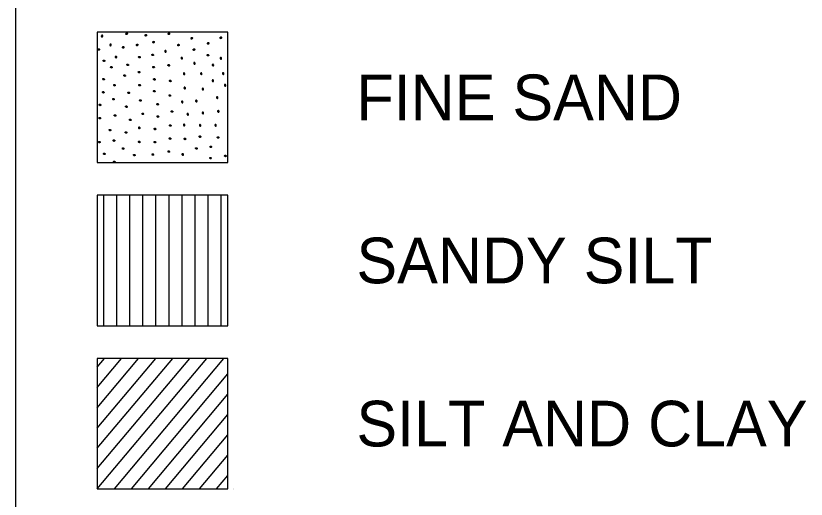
# Model space of a CAD drawing. Extents: x -59 to 43, y 0 to 22.
# Drawn here: x 11.667 to 14.091, y 17.983 to 19.465 of the extents above; entities that cross this region are included whole.
import ezdxf

# ---------------------------------------------------------------- set-up
doc = ezdxf.new("R2010")
doc.units = 0
for name, color, linetype in [('Default', 7, 'Continuous'), ('SH_Data', 7, 'Continuous'), ('SH_Text', 7, 'Continuous')]:
    doc.layers.add(name, color=color, linetype=linetype)

msp = doc.modelspace()

# ---------------------------------------------------------------- linework, layer by layer
at = {"layer": 'Default'}
for p, q in [((11.9167, 19.415), (11.9167, 19.415)), ((12.3167, 19.415), (12.3167, 19.415)), ((11.9167, 19.015), (11.9167, 19.015)), ((12.3167, 19.015), (12.3167, 19.015)), ((11.9167, 18.915), (11.9167, 18.915)), ((11.9367, 18.515), (11.9367, 18.915)), ((11.9767, 18.515), (11.9767, 18.915)), ((12.0167, 18.515), (12.0167, 18.915)), ((12.0567, 18.515), (12.0567, 18.915)), ((12.0967, 18.515), (12.0967, 18.915)), ((12.1367, 18.515), (12.1367, 18.915)), ((12.1767, 18.515), (12.1767, 18.915)), ((12.2167, 18.515), (12.2167, 18.915)), ((12.2567, 18.515), (12.2567, 18.915)), ((12.2967, 18.515), (12.2967, 18.915)), ((12.3167, 18.915), (12.3167, 18.915)), ((11.9167, 18.515), (11.9167, 18.515)), ((12.3167, 18.515), (12.3167, 18.515)), ((11.9165, 18.3259), (11.9913, 18.415)), ((11.9165, 18.2637), (12.0435, 18.415)), ((11.9165, 18.2015), (12.0957, 18.415)), ((11.9165, 18.1393), (12.148, 18.415)), ((11.9165, 18.077), (12.2002, 18.415)), ((11.9167, 18.015), (12.2524, 18.415)), ((11.9167, 18.3883), (11.9391, 18.415)), ((11.9689, 18.015), (12.3046, 18.415)), ((12.0211, 18.015), (12.3167, 18.3671)), ((12.0733, 18.015), (12.3167, 18.3049)), ((12.1256, 18.015), (12.3167, 18.2427)), ((12.1778, 18.015), (12.3167, 18.1805)), ((12.23, 18.015), (12.3167, 18.1182)), ((12.2822, 18.015), (12.3167, 18.056)), ((11.9167, 18.015), (11.9167, 18.015)), ((12.3343, 18.015), (12.3343, 18.015)), ((11.9167, 18.0128), (11.9167, 18.0128)), ((12.3345, 18.0128), (12.3345, 18.0128))]:
    msp.add_line(p, q, dxfattribs=at)
for points in [[(11.9321, 19.4006), (11.9314, 19.4003), (11.9309, 19.4001), (11.9305, 19.4001), (11.9301, 19.4003), (11.9295, 19.4009), (11.9292, 19.4013), (11.929, 19.4017), (11.9289, 19.4021), (11.9289, 19.4026), (11.9291, 19.4031), (11.9293, 19.4036), (11.9296, 19.4041), (11.93, 19.4045), (11.9305, 19.4049), (11.931, 19.4052), (11.9314, 19.4053), (11.9317, 19.4054), (11.9322, 19.4053), (11.9325, 19.4052), (11.9328, 19.4049), (11.9331, 19.4047), (11.9333, 19.4043), (11.9334, 19.404), (11.9334, 19.4037), (11.9334, 19.4033), (11.9334, 19.4031), (11.9334, 19.4028), (11.9335, 19.4025), (11.9335, 19.4022), (11.9334, 19.402), (11.9332, 19.4017), (11.9329, 19.4014), (11.9325, 19.401), (11.9321, 19.4006)], [(12.0075, 19.4077), (12.0064, 19.4072), (12.005, 19.4079), (12.0044, 19.4094), (12.0049, 19.4109), (12.0059, 19.4121), (12.0071, 19.4125), (12.0086, 19.4117), (12.0088, 19.4103), (12.0087, 19.4091), (12.0075, 19.4078)], [(12.0666, 19.403), (12.0655, 19.4025), (12.0641, 19.4031), (12.0635, 19.4047), (12.0639, 19.4061), (12.065, 19.4073), (12.0661, 19.4078), (12.0677, 19.4069), (12.0679, 19.4055), (12.0678, 19.4043), (12.0667, 19.4031)], [(12.1371, 19.4078), (12.136, 19.4072), (12.1346, 19.408), (12.134, 19.4095), (12.1345, 19.411), (12.1356, 19.4121), (12.1367, 19.4126), (12.1382, 19.4117), (12.1384, 19.4103), (12.1383, 19.4091), (12.1372, 19.4079)], [(12.2053, 19.3985), (12.2064, 19.3989), (12.2078, 19.3982), (12.2085, 19.3967), (12.208, 19.3952), (12.2069, 19.3941), (12.2058, 19.3936), (12.2042, 19.3944), (12.2041, 19.3959), (12.2041, 19.397), (12.2052, 19.3983)], [(12.2948, 19.3997), (12.2958, 19.4002), (12.2972, 19.3996), (12.2978, 19.398), (12.2974, 19.3965), (12.2963, 19.3953), (12.2952, 19.3948), (12.2936, 19.3958), (12.2934, 19.3971), (12.2935, 19.3983), (12.2947, 19.3996)], [(11.9581, 19.3737), (11.9574, 19.3734), (11.9569, 19.3732), (11.9565, 19.3732), (11.9561, 19.3735), (11.9555, 19.374), (11.9552, 19.3744), (11.955, 19.3748), (11.9549, 19.3753), (11.9549, 19.3758), (11.9551, 19.3762), (11.9553, 19.3767), (11.9556, 19.3772), (11.956, 19.3777), (11.9565, 19.3781), (11.957, 19.3783), (11.9574, 19.3785), (11.9577, 19.3785), (11.9582, 19.3784), (11.9585, 19.3783), (11.9588, 19.3781), (11.9591, 19.3778), (11.9593, 19.3775), (11.9594, 19.3771), (11.9594, 19.3768), (11.9594, 19.3765), (11.9594, 19.3762), (11.9594, 19.3759), (11.9595, 19.3756), (11.9594, 19.3754), (11.9594, 19.3752), (11.9592, 19.3749), (11.9589, 19.3745), (11.9585, 19.3741), (11.9581, 19.3737)], [(12.0396, 19.3737), (12.0386, 19.3731), (12.0371, 19.3738), (12.0365, 19.3753), (12.037, 19.3768), (12.038, 19.378), (12.0392, 19.3785), (12.0408, 19.3776), (12.0409, 19.3762), (12.0408, 19.375), (12.0397, 19.3737)], [(12.0901, 19.3819), (12.089, 19.3815), (12.0877, 19.3821), (12.087, 19.3837), (12.0875, 19.3852), (12.0886, 19.3863), (12.0897, 19.3868), (12.0912, 19.3859), (12.0914, 19.3845), (12.0914, 19.3833), (12.0902, 19.382)], [(12.1648, 19.3773), (12.1659, 19.3778), (12.1672, 19.3771), (12.1679, 19.3756), (12.1674, 19.3741), (12.1664, 19.373), (12.1652, 19.3725), (12.1636, 19.3733), (12.1634, 19.3748), (12.1635, 19.3759), (12.1647, 19.3772)], [(12.2562, 19.3826), (12.2573, 19.3831), (12.2586, 19.3825), (12.2593, 19.3809), (12.2588, 19.3794), (12.2578, 19.3783), (12.2566, 19.3778), (12.255, 19.3787), (12.2549, 19.3801), (12.2549, 19.3812), (12.2561, 19.3826)], [(11.9231, 19.3628), (11.9237, 19.3617), (11.923, 19.3602), (11.9214, 19.3596), (11.92, 19.3601), (11.9188, 19.3612), (11.9183, 19.3623), (11.9192, 19.3639), (11.9206, 19.364), (11.9218, 19.3639), (11.923, 19.3628)], [(11.997, 19.3661), (11.9959, 19.3656), (11.9945, 19.3663), (11.9938, 19.3678), (11.9944, 19.3693), (11.9954, 19.3704), (11.9966, 19.3709), (11.9981, 19.37), (11.9983, 19.3686), (11.9982, 19.3674), (11.9971, 19.3662)], [(12.1267, 19.3581), (12.1256, 19.3586), (12.1242, 19.3579), (12.1236, 19.3564), (12.1241, 19.3549), (12.1251, 19.3537), (12.1263, 19.3533), (12.1278, 19.3542), (12.128, 19.3556), (12.1279, 19.3567), (12.1267, 19.358)], [(12.2124, 19.3637), (12.2135, 19.3642), (12.2149, 19.3635), (12.2156, 19.362), (12.215, 19.3605), (12.214, 19.3593), (12.2128, 19.3589), (12.2112, 19.3597), (12.2111, 19.3611), (12.2112, 19.3623), (12.2123, 19.3636)], [(11.9392, 19.328), (11.9397, 19.3269), (11.9391, 19.3255), (11.9375, 19.3249), (11.936, 19.3254), (11.9349, 19.3264), (11.9343, 19.3276), (11.9353, 19.3292), (11.9366, 19.3293), (11.9378, 19.3292), (11.9391, 19.328)], [(11.9761, 19.3395), (11.9766, 19.3384), (11.976, 19.337), (11.9744, 19.3363), (11.9729, 19.3368), (11.9718, 19.3379), (11.9713, 19.3391), (11.9722, 19.3406), (11.9735, 19.3407), (11.9747, 19.3406), (11.9761, 19.3395)], [(12.0481, 19.3389), (12.0486, 19.3379), (12.0479, 19.3365), (12.0464, 19.3359), (12.0449, 19.3363), (12.0438, 19.3374), (12.0433, 19.3385), (12.0441, 19.3401), (12.0456, 19.3403), (12.0467, 19.3402), (12.048, 19.339)], [(12.0845, 19.3441), (12.0841, 19.3452), (12.0847, 19.3467), (12.0863, 19.3473), (12.0878, 19.3468), (12.0889, 19.3457), (12.0894, 19.3446), (12.0885, 19.343), (12.0871, 19.3429), (12.086, 19.343), (12.0846, 19.3441)], [(12.1766, 19.3372), (12.1755, 19.3377), (12.1741, 19.337), (12.1734, 19.3355), (12.1739, 19.334), (12.175, 19.3328), (12.1762, 19.3323), (12.1777, 19.3333), (12.1778, 19.3346), (12.1778, 19.3358), (12.1767, 19.3371)], [(12.2539, 19.3433), (12.2534, 19.3444), (12.2541, 19.3458), (12.2556, 19.3465), (12.2571, 19.346), (12.2582, 19.3449), (12.2587, 19.3437), (12.2578, 19.3422), (12.2564, 19.342), (12.2552, 19.3421), (12.254, 19.3433)], [(12.2966, 19.337), (12.2956, 19.3374), (12.2941, 19.3368), (12.2935, 19.3352), (12.294, 19.3337), (12.295, 19.3325), (12.2962, 19.3321), (12.2978, 19.333), (12.2979, 19.3344), (12.2978, 19.3355), (12.2967, 19.3369)], [(11.9623, 19.3079), (11.9627, 19.3069), (11.9621, 19.3055), (11.9605, 19.3048), (11.959, 19.3053), (11.9578, 19.3063), (11.9574, 19.3075), (11.9583, 19.3091), (11.9597, 19.3093), (11.9608, 19.3092), (11.9622, 19.308)], [(12.0122, 19.3152), (12.0126, 19.3142), (12.012, 19.3127), (12.0104, 19.3121), (12.0089, 19.3126), (12.0078, 19.3136), (12.0074, 19.3148), (12.0082, 19.3164), (12.0097, 19.3165), (12.0108, 19.3164), (12.0121, 19.3153)], [(12.0913, 19.3085), (12.0918, 19.3074), (12.0911, 19.306), (12.0896, 19.3054), (12.0881, 19.3059), (12.0869, 19.3069), (12.0864, 19.3081), (12.0874, 19.3096), (12.0887, 19.3098), (12.0899, 19.3097), (12.0912, 19.3085)], [(12.1381, 19.3139), (12.1386, 19.3129), (12.1378, 19.3115), (12.1364, 19.3108), (12.1349, 19.3113), (12.1337, 19.3124), (12.1332, 19.3135), (12.1341, 19.3151), (12.1355, 19.3152), (12.1367, 19.3152), (12.138, 19.3141)], [(12.2156, 19.3215), (12.2145, 19.3219), (12.213, 19.3213), (12.2124, 19.3197), (12.2129, 19.3182), (12.214, 19.317), (12.2151, 19.3166), (12.2167, 19.3175), (12.2168, 19.3189), (12.2167, 19.32), (12.2156, 19.3213)], [(12.2724, 19.316), (12.2713, 19.3165), (12.27, 19.3159), (12.2693, 19.3143), (12.2697, 19.3128), (12.2708, 19.3117), (12.272, 19.3111), (12.2735, 19.3121), (12.2737, 19.3135), (12.2736, 19.3146), (12.2725, 19.3159)], [(12.003, 19.2824), (12.0034, 19.2814), (12.0028, 19.28), (12.0012, 19.2793), (11.9997, 19.2798), (11.9986, 19.2808), (11.9982, 19.282), (11.999, 19.2836), (12.0004, 19.2837), (12.0015, 19.2837), (12.0029, 19.2825)], [(12.0471, 19.2931), (12.0476, 19.292), (12.047, 19.2907), (12.0454, 19.29), (12.0439, 19.2905), (12.0427, 19.2915), (12.0423, 19.2927), (12.0432, 19.2943), (12.0446, 19.2944), (12.0457, 19.2944), (12.0471, 19.2932)], [(12.1838, 19.2893), (12.1827, 19.2898), (12.1813, 19.2891), (12.1807, 19.2875), (12.1812, 19.2861), (12.1823, 19.2849), (12.1834, 19.2844), (12.1849, 19.2853), (12.1851, 19.2867), (12.185, 19.2879), (12.1839, 19.2892)], [(12.2364, 19.2894), (12.2353, 19.2899), (12.2339, 19.2893), (12.2333, 19.2877), (12.2338, 19.2862), (12.2348, 19.2851), (12.236, 19.2845), (12.2375, 19.2855), (12.2377, 19.2869), (12.2376, 19.288), (12.2364, 19.2893)], [(12.3036, 19.2901), (12.3025, 19.2906), (12.3011, 19.2899), (12.3005, 19.2883), (12.3009, 19.2869), (12.302, 19.2857), (12.3031, 19.2853), (12.3047, 19.2861), (12.3049, 19.2875), (12.3048, 19.2887), (12.3037, 19.29)], [(11.938, 19.2712), (11.9385, 19.2702), (11.9378, 19.2688), (11.9363, 19.2682), (11.9348, 19.2686), (11.9337, 19.2696), (11.9331, 19.2708), (11.9341, 19.2724), (11.9355, 19.2726), (11.9366, 19.2725), (11.9379, 19.2713)], [(11.9715, 19.2529), (11.972, 19.2518), (11.9713, 19.2504), (11.9698, 19.2497), (11.9683, 19.2502), (11.9671, 19.2513), (11.9667, 19.2525), (11.9675, 19.254), (11.9689, 19.2541), (11.9701, 19.2541), (11.9714, 19.253)], [(12.0483, 19.2531), (12.0489, 19.2521), (12.0482, 19.2507), (12.0467, 19.25), (12.0452, 19.2505), (12.044, 19.2515), (12.0435, 19.2527), (12.0444, 19.2543), (12.0458, 19.2544), (12.047, 19.2544), (12.0482, 19.2532)], [(12.094, 19.271), (12.0945, 19.27), (12.0938, 19.2685), (12.0923, 19.2679), (12.0908, 19.2684), (12.0897, 19.2694), (12.0892, 19.2706), (12.0901, 19.2722), (12.0915, 19.2723), (12.0927, 19.2722), (12.0939, 19.2711)], [(12.143, 19.2661), (12.1435, 19.2651), (12.1428, 19.2637), (12.1413, 19.263), (12.1398, 19.2635), (12.1386, 19.2646), (12.1382, 19.2657), (12.1391, 19.2673), (12.1404, 19.2674), (12.1416, 19.2674), (12.1429, 19.2662)], [(12.2721, 19.2681), (12.2711, 19.2685), (12.2697, 19.2679), (12.269, 19.2663), (12.2695, 19.2648), (12.2705, 19.2637), (12.2717, 19.2632), (12.2733, 19.2641), (12.2734, 19.2656), (12.2734, 19.2667), (12.2722, 19.268)], [(12.3094, 19.2544), (12.3084, 19.2548), (12.307, 19.2542), (12.3064, 19.2526), (12.3068, 19.2511), (12.3078, 19.25), (12.309, 19.2495), (12.3106, 19.2504), (12.3108, 19.2519), (12.3107, 19.253), (12.3095, 19.2543)], [(11.9372, 19.2313), (11.9377, 19.2302), (11.937, 19.2288), (11.9355, 19.2282), (11.934, 19.2287), (11.9329, 19.2297), (11.9323, 19.2309), (11.9333, 19.2324), (11.9346, 19.2326), (11.9358, 19.2325), (11.9371, 19.2314)], [(12.0151, 19.2296), (12.0156, 19.2285), (12.0149, 19.2272), (12.0134, 19.2265), (12.0119, 19.227), (12.0108, 19.2281), (12.0103, 19.2293), (12.0112, 19.2308), (12.0126, 19.231), (12.0138, 19.2309), (12.015, 19.2297)], [(12.0936, 19.2347), (12.0941, 19.2336), (12.0934, 19.2322), (12.0919, 19.2315), (12.0904, 19.2321), (12.0893, 19.2331), (12.0887, 19.2343), (12.0897, 19.2358), (12.0911, 19.236), (12.0922, 19.2359), (12.0935, 19.2348)], [(12.1856, 19.2459), (12.1845, 19.2463), (12.1831, 19.2457), (12.1825, 19.2441), (12.183, 19.2427), (12.184, 19.2415), (12.1852, 19.2411), (12.1867, 19.2419), (12.1869, 19.2433), (12.1868, 19.2444), (12.1856, 19.2458)], [(12.2413, 19.2424), (12.2403, 19.2429), (12.2389, 19.2423), (12.2383, 19.2407), (12.2387, 19.2392), (12.2398, 19.238), (12.241, 19.2375), (12.2425, 19.2385), (12.2427, 19.2398), (12.2426, 19.241), (12.2414, 19.2423)], [(11.9686, 19.2101), (11.969, 19.2091), (11.9683, 19.2077), (11.9668, 19.207), (11.9653, 19.2075), (11.9641, 19.2085), (11.9637, 19.2097), (11.9645, 19.2113), (11.966, 19.2115), (11.9671, 19.2114), (11.9684, 19.2102)], [(12.0512, 19.2063), (12.0516, 19.2053), (12.051, 19.2039), (12.0494, 19.2033), (12.0479, 19.2037), (12.0468, 19.2048), (12.0463, 19.2059), (12.0472, 19.2075), (12.0486, 19.2077), (12.0497, 19.2076), (12.0511, 19.2064)], [(12.1412, 19.2213), (12.1417, 19.2203), (12.1411, 19.2189), (12.1395, 19.2182), (12.138, 19.2187), (12.1368, 19.2197), (12.1364, 19.2209), (12.1372, 19.2225), (12.1386, 19.2226), (12.1398, 19.2226), (12.1412, 19.2214)], [(12.1782, 19.2031), (12.1771, 19.2036), (12.1757, 19.203), (12.1751, 19.2014), (12.1756, 19.1999), (12.1766, 19.1988), (12.1778, 19.1982), (12.1793, 19.1992), (12.1795, 19.2005), (12.1794, 19.2017), (12.1782, 19.203)], [(12.2213, 19.2059), (12.2202, 19.2063), (12.2188, 19.2057), (12.2182, 19.2041), (12.2186, 19.2026), (12.2197, 19.2015), (12.2208, 19.201), (12.2224, 19.2019), (12.2226, 19.2033), (12.2225, 19.2044), (12.2213, 19.2058)], [(12.2854, 19.2164), (12.2843, 19.2169), (12.2829, 19.2163), (12.2822, 19.2147), (12.2827, 19.2132), (12.2838, 19.212), (12.2849, 19.2115), (12.2865, 19.2125), (12.2866, 19.2139), (12.2866, 19.215), (12.2855, 19.2163)], [(11.9275, 19.1925), (11.9279, 19.1915), (11.9273, 19.19), (11.9257, 19.1894), (11.9242, 19.1899), (11.923, 19.191), (11.9226, 19.1921), (11.9235, 19.1937), (11.9249, 19.1938), (11.926, 19.1937), (11.9274, 19.1926)], [(12.0082, 19.1871), (12.0087, 19.186), (12.0081, 19.1847), (12.0065, 19.184), (12.005, 19.1845), (12.0038, 19.1856), (12.0034, 19.1867), (12.0043, 19.1883), (12.0057, 19.1885), (12.0068, 19.1884), (12.0082, 19.1872)], [(12.1038, 19.1945), (12.1043, 19.1934), (12.1036, 19.192), (12.1021, 19.1914), (12.1006, 19.1919), (12.0994, 19.193), (12.0989, 19.1941), (12.0998, 19.1956), (12.1012, 19.1958), (12.1024, 19.1957), (12.1037, 19.1946)], [(11.9731, 19.1602), (11.9737, 19.1592), (11.973, 19.1578), (11.9714, 19.1571), (11.97, 19.1576), (11.9688, 19.1586), (11.9683, 19.1598), (11.9692, 19.1614), (11.9706, 19.1615), (11.9718, 19.1615), (11.973, 19.1603)], [(12.0586, 19.1656), (12.059, 19.1644), (12.0584, 19.163), (12.0568, 19.1624), (12.0553, 19.1629), (12.0542, 19.164), (12.0538, 19.1651), (12.0546, 19.1667), (12.056, 19.1668), (12.0571, 19.1667), (12.0585, 19.1656)], [(12.1048, 19.1568), (12.1052, 19.1557), (12.1046, 19.1543), (12.103, 19.1537), (12.1015, 19.1541), (12.1004, 19.1552), (12.0999, 19.1563), (12.1008, 19.1579), (12.1022, 19.1581), (12.1034, 19.158), (12.1047, 19.1569)], [(12.1479, 19.1722), (12.1484, 19.1711), (12.1478, 19.1697), (12.1462, 19.1691), (12.1447, 19.1696), (12.1436, 19.1707), (12.143, 19.1718), (12.144, 19.1733), (12.1454, 19.1735), (12.1465, 19.1734), (12.1478, 19.1723)], [(12.1949, 19.1653), (12.1938, 19.1658), (12.1925, 19.1652), (12.1918, 19.1636), (12.1923, 19.1621), (12.1934, 19.161), (12.1945, 19.1605), (12.196, 19.1614), (12.1962, 19.1628), (12.1961, 19.1639), (12.195, 19.1652)], [(12.2416, 19.1692), (12.2405, 19.1696), (12.2391, 19.169), (12.2385, 19.1674), (12.2389, 19.1659), (12.2401, 19.1648), (12.2412, 19.1643), (12.2427, 19.1652), (12.2429, 19.1667), (12.2428, 19.1678), (12.2417, 19.1691)], [(12.2887, 19.1741), (12.2877, 19.1745), (12.2863, 19.1739), (12.2856, 19.1723), (12.2861, 19.1708), (12.2872, 19.1697), (12.2883, 19.1692), (12.2899, 19.1701), (12.2901, 19.1715), (12.29, 19.1726), (12.2888, 19.174)], [(11.9265, 19.1521), (11.927, 19.151), (11.9264, 19.1496), (11.9248, 19.149), (11.9233, 19.1495), (11.9222, 19.1505), (11.9217, 19.1517), (11.9226, 19.1533), (11.924, 19.1534), (11.9251, 19.1533), (11.9264, 19.1522)], [(12.0198, 19.1467), (12.0204, 19.1456), (12.0197, 19.1443), (12.0181, 19.1437), (12.0166, 19.1441), (12.0155, 19.1452), (12.015, 19.1463), (12.0159, 19.1479), (12.0173, 19.1481), (12.0185, 19.148), (12.0197, 19.1468)], [(12.1427, 19.1293), (12.1431, 19.1282), (12.1425, 19.1268), (12.1409, 19.1262), (12.1394, 19.1267), (12.1382, 19.1278), (12.1378, 19.1289), (12.1387, 19.1304), (12.1401, 19.1306), (12.1412, 19.1305), (12.1426, 19.1294)], [(12.184, 19.1321), (12.1829, 19.1326), (12.1815, 19.1319), (12.1808, 19.1304), (12.1814, 19.1289), (12.1824, 19.1277), (12.1836, 19.1272), (12.1851, 19.1282), (12.1852, 19.1295), (12.1852, 19.1307), (12.1841, 19.132)], [(12.2329, 19.1311), (12.2319, 19.1316), (12.2304, 19.131), (12.2298, 19.1294), (12.2303, 19.1279), (12.2313, 19.1268), (12.2325, 19.1263), (12.2341, 19.1272), (12.2342, 19.1286), (12.2341, 19.1297), (12.233, 19.1311)], [(12.2804, 19.1314), (12.2793, 19.1319), (12.2778, 19.1312), (12.2772, 19.1296), (12.2777, 19.1282), (12.2788, 19.127), (12.2799, 19.1266), (12.2815, 19.1274), (12.2816, 19.1289), (12.2815, 19.13), (12.2804, 19.1313)], [(11.9576, 19.1155), (11.9582, 19.1145), (11.9575, 19.113), (11.9559, 19.1124), (11.9545, 19.1129), (11.9533, 19.1139), (11.9528, 19.1151), (11.9537, 19.1167), (11.9551, 19.1168), (11.9563, 19.1167), (11.9575, 19.1156)], [(12.0068, 19.1081), (12.0074, 19.107), (12.0067, 19.1056), (12.0051, 19.105), (12.0037, 19.1055), (12.0025, 19.1065), (12.002, 19.1077), (12.0029, 19.1093), (12.0043, 19.1094), (12.0055, 19.1093), (12.0067, 19.1082)], [(12.0475, 19.1221), (12.048, 19.121), (12.0474, 19.1196), (12.0458, 19.1189), (12.0443, 19.1194), (12.0432, 19.1205), (12.0427, 19.1216), (12.0436, 19.1232), (12.045, 19.1233), (12.0461, 19.1233), (12.0475, 19.1221)], [(12.0957, 19.1189), (12.0962, 19.1178), (12.0956, 19.1164), (12.094, 19.1157), (12.0925, 19.1163), (12.0914, 19.1173), (12.0909, 19.1185), (12.0918, 19.12), (12.0932, 19.1202), (12.0943, 19.1201), (12.0956, 19.1189)], [(11.97, 19.0833), (11.9704, 19.0822), (11.9698, 19.0807), (11.9682, 19.0801), (11.9667, 19.0806), (11.9656, 19.0817), (11.9651, 19.0829), (11.966, 19.0844), (11.9674, 19.0845), (11.9686, 19.0845), (11.9698, 19.0833)], [(12.142, 19.0895), (12.1425, 19.0884), (12.1419, 19.087), (12.1403, 19.0863), (12.1388, 19.0868), (12.1377, 19.0879), (12.1371, 19.089), (12.1381, 19.0906), (12.1395, 19.0907), (12.1406, 19.0907), (12.1419, 19.0896)], [(12.1877, 19.0884), (12.1882, 19.0873), (12.1875, 19.0859), (12.186, 19.0852), (12.1845, 19.0858), (12.1834, 19.0868), (12.1829, 19.088), (12.1838, 19.0896), (12.1852, 19.0897), (12.1864, 19.0896), (12.1876, 19.0885)], [(12.2338, 19.0953), (12.2343, 19.0943), (12.2336, 19.0929), (12.232, 19.0922), (12.2306, 19.0927), (12.2294, 19.0938), (12.2289, 19.0949), (12.2298, 19.0965), (12.2312, 19.0967), (12.2324, 19.0966), (12.2337, 19.0954)], [(12.2895, 19.0929), (12.29, 19.0918), (12.2893, 19.0904), (12.2878, 19.0897), (12.2863, 19.0902), (12.2851, 19.0913), (12.2846, 19.0925), (12.2856, 19.094), (12.2869, 19.0941), (12.2881, 19.0941), (12.2894, 19.093)], [(11.9251, 19.0785), (11.9256, 19.0775), (11.9249, 19.0761), (11.9234, 19.0755), (11.9219, 19.0759), (11.9208, 19.077), (11.9202, 19.0782), (11.9212, 19.0797), (11.9226, 19.0799), (11.9237, 19.0798), (11.925, 19.0786)], [(11.9982, 19.0588), (11.9986, 19.0577), (11.998, 19.0563), (11.9964, 19.0556), (11.995, 19.0561), (11.9938, 19.0572), (11.9934, 19.0583), (11.9942, 19.0599), (11.9956, 19.06), (11.9967, 19.06), (11.9981, 19.0589)], [(12.0476, 19.0791), (12.0481, 19.0781), (12.0475, 19.0767), (12.0459, 19.076), (12.0444, 19.0765), (12.0432, 19.0775), (12.0427, 19.0787), (12.0436, 19.0803), (12.045, 19.0804), (12.0462, 19.0804), (12.0475, 19.0792)], [(12.0955, 19.0785), (12.096, 19.0774), (12.0953, 19.0761), (12.0938, 19.0754), (12.0923, 19.0759), (12.0912, 19.077), (12.0907, 19.0782), (12.0915, 19.0797), (12.093, 19.0799), (12.0941, 19.0798), (12.0955, 19.0786)], [(12.2227, 19.0594), (12.2232, 19.0583), (12.2226, 19.0569), (12.221, 19.0563), (12.2196, 19.0567), (12.2184, 19.0578), (12.2179, 19.059), (12.2188, 19.0605), (12.2202, 19.0607), (12.2213, 19.0607), (12.2226, 19.0595)], [(12.2671, 19.0643), (12.2676, 19.0632), (12.267, 19.0619), (12.2654, 19.0611), (12.2639, 19.0616), (12.2627, 19.0627), (12.2623, 19.0639), (12.2632, 19.0654), (12.2645, 19.0656), (12.2657, 19.0656), (12.2671, 19.0644)], [(11.9401, 19.0427), (11.9407, 19.0417), (11.94, 19.0403), (11.9384, 19.0396), (11.937, 19.0401), (11.9358, 19.0412), (11.9353, 19.0423), (11.9362, 19.0439), (11.9376, 19.0441), (11.9388, 19.044), (11.9401, 19.0429)], [(12.0323, 19.0389), (12.0328, 19.0378), (12.0321, 19.0364), (12.0306, 19.0357), (12.0291, 19.0363), (12.0279, 19.0373), (12.0275, 19.0385), (12.0284, 19.04), (12.0297, 19.0402), (12.0309, 19.04), (12.0322, 19.0389)], [(12.0892, 19.0403), (12.0897, 19.0393), (12.089, 19.0378), (12.0875, 19.0372), (12.086, 19.0377), (12.0849, 19.0387), (12.0844, 19.0399), (12.0852, 19.0415), (12.0867, 19.0416), (12.0878, 19.0415), (12.0892, 19.0404)], [(12.1382, 19.0495), (12.1387, 19.0485), (12.1381, 19.047), (12.1365, 19.0464), (12.1351, 19.0469), (12.1339, 19.048), (12.1334, 19.0491), (12.1343, 19.0507), (12.1357, 19.0508), (12.1369, 19.0507), (12.1382, 19.0496)], [(12.1808, 19.0407), (12.1814, 19.0396), (12.1807, 19.0382), (12.1791, 19.0375), (12.1777, 19.038), (12.1765, 19.0391), (12.176, 19.0403), (12.1769, 19.0418), (12.1783, 19.0419), (12.1795, 19.0419), (12.1808, 19.0407)], [(12.312, 19.0361), (12.3125, 19.0351), (12.3118, 19.0337), (12.3103, 19.033), (12.3088, 19.0335), (12.3076, 19.0345), (12.3071, 19.0357), (12.3081, 19.0373), (12.3094, 19.0374), (12.3106, 19.0374), (12.3119, 19.0362)], [(11.9712, 19.0181), (11.9716, 19.017), (11.9709, 19.0156), (11.9694, 19.015), (11.9679, 19.0155), (11.9667, 19.0166), (11.9663, 19.0177), (11.9671, 19.0192), (11.9686, 19.0194), (11.9697, 19.0193), (11.9711, 19.0182)], [(12.266, 19.0298), (12.2665, 19.0287), (12.2659, 19.0274), (12.2643, 19.0267), (12.2628, 19.0272), (12.2617, 19.0282), (12.2612, 19.0294), (12.2621, 19.031), (12.2635, 19.0311), (12.2646, 19.0311), (12.266, 19.0299)]]:
    msp.add_spline(points, degree=3, dxfattribs=at)
at = {"layer": 'SH_Data'}
msp.add_line((11.6667, 5.18), (11.6667, 21), dxfattribs=at)
for points in [[(11.9167, 19.015), (12.3167, 19.015), (12.3167, 19.415), (11.9167, 19.415)], [(11.9167, 18.515), (12.3167, 18.515), (12.3167, 18.915), (11.9167, 18.915)], [(11.9167, 18.015), (12.3167, 18.015), (12.3167, 18.415), (11.9167, 18.415)]]:
    msp.add_lwpolyline(points, close=True, dxfattribs=at)

# ---------------------------------------------------------------- texts
at = {"layer": 'SH_Text'}
for s, p in [('FINE SAND', (12.7116, 19.145)), ('SANDY SILT', (12.7116, 18.645)), ('SILT AND CLAY', (12.7116, 18.145))]:
    msp.add_text(s, height=0.14, dxfattribs=at).set_placement(p)

doc.saveas('drawing.dxf')
